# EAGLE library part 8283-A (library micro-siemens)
MICROPROCESSOR/PERIPHERAL DEVICE
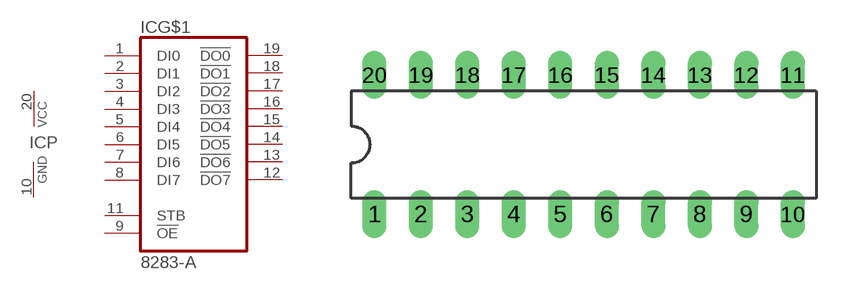
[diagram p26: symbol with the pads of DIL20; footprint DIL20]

Designator prefix IC; gates G$1=8283-A P=VCCGND

## 8283-A (OC_FARNELL: unknown; OC_NEWARK: unknown)  [DIL20]
1  G$1:DI0  in
2  G$1:DI1  in
3  G$1:DI2  in
4  G$1:DI3  in
5  G$1:DI4  in
6  G$1:DI5  in
7  G$1:DI6  in
8  G$1:DI7  in
9  G$1:!OE  in
10  P:GND  pwr
11  G$1:STB  in
12  G$1:!DO7  out
13  G$1:!DO6  out
14  G$1:!DO5  out
15  G$1:!DO4  out
16  G$1:!DO3  out
17  G$1:!DO2  out
18  G$1:!DO1  out
19  G$1:!DO0  out
20  P:VCC  pwr

## Footprint DIL20 (pad centres in mm)
Dual In Line Package
drill 0.813 long: 1 -11.43,-3.81; 2 -8.89,-3.81; 3 -6.35,-3.81; 4 -3.81,-3.81; 5 -1.27,-3.81; 6 1.27,-3.81; 7 3.81,-3.81; 8 6.35,-3.81; 9 8.89,-3.81; 10 11.43,-3.81; 11 11.43,3.81; 12 8.89,3.81; 13 6.35,3.81; 14 3.81,3.81; 15 1.27,3.81; 16 -1.27,3.81; 17 -3.81,3.81; 18 -6.35,3.81; 19 -8.89,3.81; 20 -11.43,3.81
